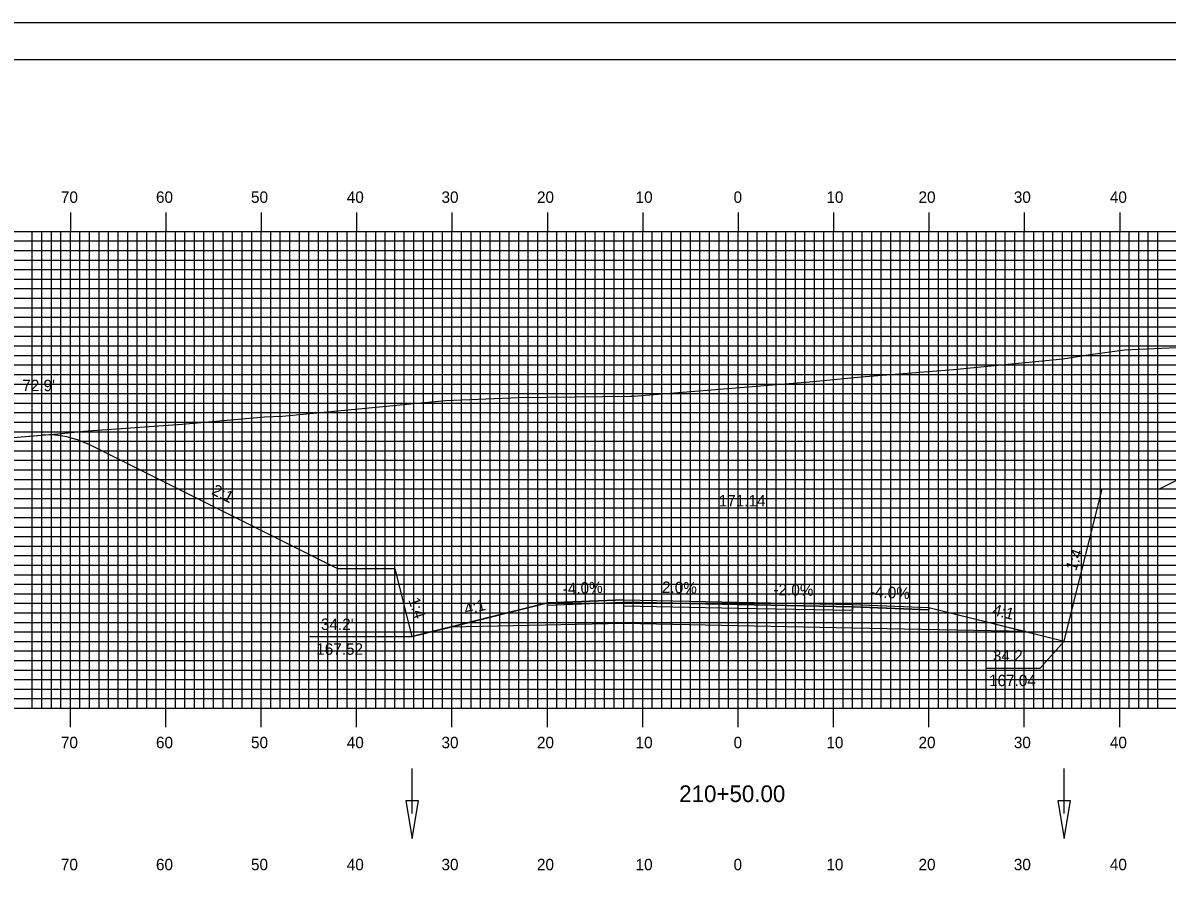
# Model space of a CAD drawing. Extents: x 1794453 to 1794796, y 442591 to 442811.
# Drawn here: x 1794543.4 to 1794663.3, y 442721.2 to 442810.5 of the extents above; entities that cross this region are included whole.
import ezdxf

# ---------------------------------------------------------------- set-up
doc = ezdxf.new("R2010")
doc.units = 0
for name, color, linetype in [('ANNOTATION', 7, 'Continuous'), ('BORDER', 7, 'Continuous'), ('D_Drainage_Ditch_Line', 7, 'Continuous'), ('D_Roadway_Centerline', 7, 'Continuous'), ('D_Roadway_Centerline_Text', 7, 'Continuous'), ('D_Roadway_Edge_Shoulder', 7, 'Continuous'), ('D_Roadway_Edge_TW', 7, 'Continuous'), ('D_Roadway_FinishedGrade', 7, 'Continuous'), ('D_Roadway_Pavement', 7, 'Continuous'), ('D_Roadway_SlopeLines', 7, 'Continuous'), ('D_Roadway_SubGrade', 7, 'Continuous'), ('D_Text_Standard', 7, 'Continuous'), ('H_V ANNOTATION', 7, 'Continuous'), ('MAJOR', 7, 'Continuous'), ('MINOR', 7, 'Continuous'), ('PDRAIN', 7, 'Continuous'), ('PLOT BOUNDARY', 7, 'Continuous'), ('S_Roadway_Centerline', 7, 'Continuous')]:
    doc.layers.add(name, color=color, linetype=linetype)

msp = doc.modelspace()

# ---------------------------------------------------------------- linework, layer by layer
at = {"layer": 'ANNOTATION'}
msp.add_lwpolyline([(1794644.32, 442742.86), (1794650.01, 442742.86), (1794652.51, 442745.7)], dxfattribs=at)
at = {"layer": 'BORDER'}
msp.add_lwpolyline([(1794468.74, 442596.67), (1794788.74, 442596.67), (1794788.74, 442806.67), (1794468.74, 442806.67)], close=True, dxfattribs=at)
at = {"layer": 'D_Drainage_Ditch_Line'}
for p, q in [((1794584.17, 442727.63), (1794584.17, 442732.33)), ((1794652.51, 442727.63), (1794652.51, 442732.33))]:
    msp.add_line(p, q, dxfattribs=at)
for points in [[(1794584.82, 442728.94), (1794583.51, 442728.94), (1794584.17, 442725)], [(1794653.17, 442728.94), (1794651.86, 442728.94), (1794652.51, 442725)]]:
    msp.add_lwpolyline(points, close=True, dxfattribs=at)
at = {"layer": 'D_Roadway_Centerline'}
msp.add_lwpolyline([(1794584.17, 442746.18), (1794588.17, 442747.18), (1794598.34, 442749.72), (1794606.34, 442750.04), (1794618.34, 442749.8), (1794630.34, 442749.56), (1794638.34, 442749.24), (1794648.51, 442746.7), (1794652.51, 442745.7)], dxfattribs=at)
at = {"layer": 'D_Roadway_Edge_Shoulder'}
for points in [[(1794606.34, 442750.04), (1794598.34, 442749.72), (1794598.34, 442749.47), (1794606.34, 442749.79)], [(1794630.34, 442749.56), (1794638.34, 442749.24), (1794638.34, 442748.99), (1794630.34, 442749.31)]]:
    msp.add_lwpolyline(points, close=True, dxfattribs=at)
at = {"layer": 'D_Roadway_Edge_TW'}
msp.add_lwpolyline([(1794606.34, 442749.79), (1794606.34, 442750.04), (1794618.34, 442749.8), (1794630.34, 442749.56), (1794630.34, 442749.31), (1794618.34, 442749.55)], close=True, dxfattribs=at)
at = {"layer": 'D_Roadway_FinishedGrade'}
msp.add_arc((1794545.9, 442757.33), 10, 63.4349, 92.7287, dxfattribs=at)
at = {"layer": 'D_Roadway_Pavement'}
msp.add_lwpolyline([(1794606.34, 442749.38), (1794606.34, 442749.79), (1794618.34, 442749.55), (1794630.34, 442749.31), (1794630.34, 442748.9), (1794618.34, 442749.14)], close=True, dxfattribs=at)
at = {"layer": 'D_Roadway_SlopeLines'}
for p, q in [((1794662.5, 442761.67), (1794686.86, 442773.84)), ((1794652.51, 442745.7), (1794656.5, 442761.67)), ((1794656.5, 442761.67), (1794662.5, 442761.67))]:
    msp.add_line(p, q, dxfattribs=at)
for points in [[(1794582.39, 442753.27), (1794576.39, 442753.27), (1794550.37, 442766.28)], [(1794584.17, 442746.18), (1794582.39, 442753.27), (1794576.39, 442753.27)], [(1794598.34, 442749.72), (1794584.17, 442746.18)], [(1794638.34, 442749.24), (1794652.51, 442745.7)]]:
    msp.add_lwpolyline(points, dxfattribs=at)
at = {"layer": 'D_Roadway_SubGrade'}
msp.add_lwpolyline([(1794606.34, 442747.54), (1794588.17, 442747.18), (1794598.34, 442749.72), (1794598.34, 442749.47), (1794606.34, 442749.79), (1794618.34, 442749.55), (1794630.34, 442749.31), (1794638.34, 442748.99), (1794638.34, 442749.24), (1794648.51, 442746.7), (1794630.34, 442747.06), (1794618.34, 442747.3)], close=True, dxfattribs=at)
at = {"layer": 'MAJOR'}
for p, q in [((1794548.34, 442790.67), (1794548.34, 442788.67)), ((1794558.34, 442790.67), (1794558.34, 442788.67)), ((1794568.34, 442790.67), (1794568.34, 442788.67)), ((1794578.34, 442790.67), (1794578.34, 442788.67)), ((1794588.34, 442790.67), (1794588.34, 442788.67)), ((1794598.34, 442790.67), (1794598.34, 442788.67)), ((1794608.34, 442790.67), (1794608.34, 442788.67)), ((1794618.34, 442790.67), (1794618.34, 442788.67)), ((1794628.34, 442790.67), (1794628.34, 442788.67)), ((1794638.34, 442790.67), (1794638.34, 442788.67)), ((1794648.34, 442790.67), (1794648.34, 442788.67)), ((1794658.34, 442790.67), (1794658.34, 442788.67)), ((1794478.34, 442788.67), (1794758.34, 442788.67)), ((1794478.34, 442788.67), (1794758.34, 442788.67)), ((1794548.34, 442738.67), (1794548.34, 442788.67)), ((1794558.34, 442738.67), (1794558.34, 442788.67)), ((1794568.34, 442738.67), (1794568.34, 442788.67)), ((1794578.34, 442738.67), (1794578.34, 442788.67)), ((1794588.34, 442738.67), (1794588.34, 442788.67)), ((1794598.34, 442738.67), (1794598.34, 442788.67)), ((1794608.34, 442738.67), (1794608.34, 442788.67)), ((1794618.34, 442738.67), (1794618.34, 442788.67)), ((1794628.34, 442738.67), (1794628.34, 442788.67)), ((1794638.34, 442738.67), (1794638.34, 442788.67)), ((1794648.34, 442738.67), (1794648.34, 442788.67)), ((1794658.34, 442738.67), (1794658.34, 442788.67)), ((1794478.34, 442783.67), (1794758.34, 442783.67)), ((1794478.34, 442778.67), (1794758.34, 442778.67)), ((1794478.34, 442773.67), (1794758.34, 442773.67)), ((1794478.34, 442768.67), (1794758.34, 442768.67)), ((1794478.34, 442763.67), (1794758.34, 442763.67)), ((1794478.34, 442758.67), (1794758.34, 442758.67)), ((1794478.34, 442753.67), (1794758.34, 442753.67)), ((1794478.34, 442748.67), (1794758.34, 442748.67)), ((1794478.34, 442743.67), (1794758.34, 442743.67)), ((1794478.34, 442738.67), (1794758.34, 442738.67)), ((1794478.34, 442738.67), (1794758.34, 442738.67)), ((1794548.34, 442736.66), (1794548.34, 442738.67)), ((1794558.34, 442736.66), (1794558.34, 442738.67)), ((1794568.34, 442736.66), (1794568.34, 442738.67)), ((1794578.34, 442736.66), (1794578.34, 442738.67)), ((1794588.34, 442736.66), (1794588.34, 442738.67)), ((1794598.34, 442736.66), (1794598.34, 442738.67)), ((1794608.34, 442736.66), (1794608.34, 442738.67)), ((1794618.34, 442736.66), (1794618.34, 442738.67)), ((1794628.34, 442736.66), (1794628.34, 442738.67)), ((1794638.34, 442736.66), (1794638.34, 442738.67)), ((1794648.34, 442736.66), (1794648.34, 442738.67)), ((1794658.34, 442736.66), (1794658.34, 442738.67))]:
    msp.add_line(p, q, dxfattribs=at)
at = {"layer": 'MINOR'}
for p, q in [((1794544.34, 442738.67), (1794544.34, 442788.67)), ((1794545.34, 442738.67), (1794545.34, 442788.67)), ((1794546.34, 442738.67), (1794546.34, 442788.67)), ((1794547.34, 442738.67), (1794547.34, 442788.67)), ((1794549.34, 442738.67), (1794549.34, 442788.67)), ((1794550.34, 442738.67), (1794550.34, 442788.67)), ((1794551.34, 442738.67), (1794551.34, 442788.67)), ((1794552.34, 442738.67), (1794552.34, 442788.67)), ((1794553.34, 442738.67), (1794553.34, 442788.67)), ((1794554.34, 442738.67), (1794554.34, 442788.67)), ((1794555.34, 442738.67), (1794555.34, 442788.67)), ((1794556.34, 442738.67), (1794556.34, 442788.67)), ((1794557.34, 442738.67), (1794557.34, 442788.67)), ((1794559.34, 442738.67), (1794559.34, 442788.67)), ((1794560.34, 442738.67), (1794560.34, 442788.67)), ((1794561.34, 442738.67), (1794561.34, 442788.67)), ((1794562.34, 442738.67), (1794562.34, 442788.67)), ((1794563.34, 442738.67), (1794563.34, 442788.67)), ((1794564.34, 442738.67), (1794564.34, 442788.67)), ((1794565.34, 442738.67), (1794565.34, 442788.67)), ((1794566.34, 442738.67), (1794566.34, 442788.67)), ((1794567.34, 442738.67), (1794567.34, 442788.67)), ((1794569.34, 442738.67), (1794569.34, 442788.67)), ((1794570.34, 442738.67), (1794570.34, 442788.67)), ((1794571.34, 442738.67), (1794571.34, 442788.67)), ((1794572.34, 442738.67), (1794572.34, 442788.67)), ((1794573.34, 442738.67), (1794573.34, 442788.67)), ((1794574.34, 442738.67), (1794574.34, 442788.67)), ((1794575.34, 442738.67), (1794575.34, 442788.67)), ((1794576.34, 442738.67), (1794576.34, 442788.67)), ((1794577.34, 442738.67), (1794577.34, 442788.67)), ((1794579.34, 442738.67), (1794579.34, 442788.67)), ((1794580.34, 442738.67), (1794580.34, 442788.67)), ((1794581.34, 442738.67), (1794581.34, 442788.67)), ((1794582.34, 442738.67), (1794582.34, 442788.67)), ((1794583.34, 442738.67), (1794583.34, 442788.67)), ((1794584.34, 442738.67), (1794584.34, 442788.67)), ((1794585.34, 442738.67), (1794585.34, 442788.67)), ((1794586.34, 442738.67), (1794586.34, 442788.67)), ((1794587.34, 442738.67), (1794587.34, 442788.67)), ((1794589.34, 442738.67), (1794589.34, 442788.67)), ((1794590.34, 442738.67), (1794590.34, 442788.67)), ((1794591.34, 442738.67), (1794591.34, 442788.67)), ((1794592.34, 442738.67), (1794592.34, 442788.67)), ((1794593.34, 442738.67), (1794593.34, 442788.67)), ((1794594.34, 442738.67), (1794594.34, 442788.67)), ((1794595.34, 442738.67), (1794595.34, 442788.67)), ((1794596.34, 442738.67), (1794596.34, 442788.67)), ((1794597.34, 442738.67), (1794597.34, 442788.67)), ((1794599.34, 442738.67), (1794599.34, 442788.67)), ((1794600.34, 442738.67), (1794600.34, 442788.67)), ((1794601.34, 442738.67), (1794601.34, 442788.67)), ((1794602.34, 442738.67), (1794602.34, 442788.67)), ((1794603.34, 442738.67), (1794603.34, 442788.67)), ((1794604.34, 442738.67), (1794604.34, 442788.67)), ((1794605.34, 442738.67), (1794605.34, 442788.67)), ((1794606.34, 442738.67), (1794606.34, 442788.67)), ((1794607.34, 442738.67), (1794607.34, 442788.67)), ((1794609.34, 442738.67), (1794609.34, 442788.67)), ((1794610.34, 442738.67), (1794610.34, 442788.67)), ((1794611.34, 442738.67), (1794611.34, 442788.67)), ((1794612.34, 442738.67), (1794612.34, 442788.67)), ((1794613.34, 442738.67), (1794613.34, 442788.67)), ((1794614.34, 442738.67), (1794614.34, 442788.67)), ((1794615.34, 442738.67), (1794615.34, 442788.67)), ((1794616.34, 442738.67), (1794616.34, 442788.67)), ((1794617.34, 442738.67), (1794617.34, 442788.67)), ((1794619.34, 442738.67), (1794619.34, 442788.67)), ((1794620.34, 442738.67), (1794620.34, 442788.67)), ((1794621.34, 442738.67), (1794621.34, 442788.67)), ((1794622.34, 442738.67), (1794622.34, 442788.67)), ((1794623.34, 442738.67), (1794623.34, 442788.67)), ((1794624.34, 442738.67), (1794624.34, 442788.67)), ((1794625.34, 442738.67), (1794625.34, 442788.67)), ((1794626.34, 442738.67), (1794626.34, 442788.67)), ((1794627.34, 442738.67), (1794627.34, 442788.67)), ((1794629.34, 442738.67), (1794629.34, 442788.67)), ((1794630.34, 442738.67), (1794630.34, 442788.67)), ((1794631.34, 442738.67), (1794631.34, 442788.67)), ((1794632.34, 442738.67), (1794632.34, 442788.67)), ((1794633.34, 442738.67), (1794633.34, 442788.67)), ((1794634.34, 442738.67), (1794634.34, 442788.67)), ((1794635.34, 442738.67), (1794635.34, 442788.67)), ((1794636.34, 442738.67), (1794636.34, 442788.67)), ((1794637.34, 442738.67), (1794637.34, 442788.67)), ((1794639.34, 442738.67), (1794639.34, 442788.67)), ((1794640.34, 442738.67), (1794640.34, 442788.67)), ((1794641.34, 442738.67), (1794641.34, 442788.67)), ((1794642.34, 442738.67), (1794642.34, 442788.67)), ((1794643.34, 442738.67), (1794643.34, 442788.67)), ((1794644.34, 442738.67), (1794644.34, 442788.67)), ((1794645.34, 442738.67), (1794645.34, 442788.67)), ((1794646.34, 442738.67), (1794646.34, 442788.67)), ((1794647.34, 442738.67), (1794647.34, 442788.67)), ((1794649.34, 442738.67), (1794649.34, 442788.67)), ((1794650.34, 442738.67), (1794650.34, 442788.67)), ((1794651.34, 442738.67), (1794651.34, 442788.67)), ((1794652.34, 442738.67), (1794652.34, 442788.67)), ((1794653.34, 442738.67), (1794653.34, 442788.67)), ((1794654.34, 442738.67), (1794654.34, 442788.67)), ((1794655.34, 442738.67), (1794655.34, 442788.67)), ((1794656.34, 442738.67), (1794656.34, 442788.67)), ((1794657.34, 442738.67), (1794657.34, 442788.67)), ((1794659.34, 442738.67), (1794659.34, 442788.67)), ((1794660.34, 442738.67), (1794660.34, 442788.67)), ((1794661.34, 442738.67), (1794661.34, 442788.67)), ((1794662.34, 442738.67), (1794662.34, 442788.67)), ((1794478.34, 442787.67), (1794758.34, 442787.67)), ((1794478.34, 442786.67), (1794758.34, 442786.67)), ((1794478.34, 442785.67), (1794758.34, 442785.67)), ((1794478.34, 442784.67), (1794758.34, 442784.67)), ((1794478.34, 442782.67), (1794758.34, 442782.67)), ((1794478.34, 442781.67), (1794758.34, 442781.67)), ((1794478.34, 442780.67), (1794758.34, 442780.67)), ((1794478.34, 442779.67), (1794758.34, 442779.67)), ((1794478.34, 442777.67), (1794758.34, 442777.67)), ((1794478.34, 442776.67), (1794758.34, 442776.67)), ((1794478.34, 442775.67), (1794758.34, 442775.67)), ((1794478.34, 442774.67), (1794758.34, 442774.67)), ((1794478.34, 442772.67), (1794758.34, 442772.67)), ((1794478.34, 442771.67), (1794758.34, 442771.67)), ((1794478.34, 442770.67), (1794758.34, 442770.67)), ((1794478.34, 442769.67), (1794758.34, 442769.67)), ((1794478.34, 442767.67), (1794758.34, 442767.67)), ((1794478.34, 442766.67), (1794758.34, 442766.67)), ((1794478.34, 442765.67), (1794758.34, 442765.67)), ((1794478.34, 442764.67), (1794758.34, 442764.67)), ((1794478.34, 442762.67), (1794758.34, 442762.67)), ((1794478.34, 442761.67), (1794758.34, 442761.67)), ((1794478.34, 442760.67), (1794758.34, 442760.67)), ((1794478.34, 442759.67), (1794758.34, 442759.67)), ((1794478.34, 442757.67), (1794758.34, 442757.67)), ((1794478.34, 442756.67), (1794758.34, 442756.67)), ((1794478.34, 442755.67), (1794758.34, 442755.67)), ((1794478.34, 442754.67), (1794758.34, 442754.67)), ((1794478.34, 442752.67), (1794758.34, 442752.67)), ((1794478.34, 442751.67), (1794758.34, 442751.67)), ((1794478.34, 442750.67), (1794758.34, 442750.67)), ((1794478.34, 442749.67), (1794758.34, 442749.67)), ((1794478.34, 442747.67), (1794758.34, 442747.67)), ((1794478.34, 442746.67), (1794758.34, 442746.67)), ((1794478.34, 442745.67), (1794758.34, 442745.67)), ((1794478.34, 442744.67), (1794758.34, 442744.67)), ((1794478.34, 442742.67), (1794758.34, 442742.67)), ((1794478.34, 442741.67), (1794758.34, 442741.67)), ((1794478.34, 442740.67), (1794758.34, 442740.67)), ((1794478.34, 442739.67), (1794758.34, 442739.67))]:
    msp.add_line(p, q, dxfattribs=at)
at = {"layer": 'PDRAIN'}
msp.add_line((1794573.44, 442746.18), (1794584.17, 442746.18), dxfattribs=at)
at = {"layer": 'PLOT BOUNDARY'}
msp.add_lwpolyline([(1794452.55, 442590.55), (1794792.55, 442590.55), (1794792.55, 442810.55), (1794452.55, 442810.55)], close=True, dxfattribs=at)
at = {"layer": 'S_Roadway_Centerline'}
msp.add_lwpolyline([(1794541.92, 442767.04), (1794547.45, 442767.48), (1794549.7, 442767.71), (1794560.05, 442768.47), (1794568.69, 442769.23), (1794570.58, 442769.31), (1794574.18, 442769.66), (1794587.66, 442770.93), (1794595.36, 442771.27), (1794607.06, 442771.39), (1794607.36, 442771.41), (1794625.82, 442772.9), (1794631.23, 442773.41), (1794640.93, 442774.18), (1794644.86, 442774.57), (1794652.38, 442775.32), (1794655.23, 442775.75), (1794658.84, 442776.27), (1794665.09, 442776.54)], dxfattribs=at)

# ---------------------------------------------------------------- texts
at = {"layer": 'ANNOTATION'}
for s, rotation, p in [('2:1', 333.4349, (1794563.05, 442761.15)), ('2:1', 333.4349, (1794563.05, 442761.15)), ('1:4', 70.516, (1794653.76, 442752.99)), ('1:4', 70.516, (1794653.76, 442752.99)), ('-4.0%', 2.2906, (1794599.97, 442750.59)), ('2.0%', 358.8542, (1794610.35, 442750.76)), ('-2.0%', 358.8542, (1794622.03, 442750.53)), ('-4.0%', 357.7094, (1794632.13, 442750.29)), ('1:4', 289.484, (1794583.74, 442750.04)), ('1:4', 289.484, (1794583.74, 442750.04)), ('4:1', 14.0362, (1794589.79, 442748.45)), ('4:1', 345.9638, (1794644.93, 442748.46))]:
    msp.add_text(s, height=1.2, rotation=rotation, dxfattribs=at).set_placement(p)
for s, p in [("34.2'", (1794574.6, 442746.87)), ('167.52', (1794574.11, 442744.27)), ("34.2'", (1794645.05, 442743.58)), ('167.04', (1794644.64, 442740.98))]:
    msp.add_text(s, height=1.2, dxfattribs=at).set_placement(p)
at = {"layer": 'D_Roadway_Centerline'}
for s, p in [('C', (1794618.33, 442749.8)), ('L', (1794618.34, 442749.8))]:
    msp.add_text(s, height=0.0146, dxfattribs=at).set_placement(p)
at = {"layer": 'D_Roadway_Centerline_Text'}
msp.add_text('171.14', height=1.2, dxfattribs=at).set_placement((1794616.3, 442759.83))
at = {"layer": 'D_Text_Standard'}
msp.add_text("72.9'", height=1.2, dxfattribs=at).set_placement((1794543.29, 442771.92))
at = {"layer": 'H_V ANNOTATION'}
for s, height, p in [('70', 1.2, (1794547.34, 442791.67)), ('60', 1.2, (1794557.31, 442791.67)), ('50', 1.2, (1794567.27, 442791.67)), ('40', 1.2, (1794577.31, 442791.67)), ('30', 1.2, (1794587.24, 442791.67)), ('20', 1.2, (1794597.25, 442791.67)), ('10', 1.2, (1794607.59, 442791.67)), ('0', 1.2, (1794617.86, 442791.67)), ('10', 1.2, (1794627.59, 442791.67)), ('20', 1.2, (1794637.25, 442791.67)), ('30', 1.2, (1794647.24, 442791.67)), ('40', 1.2, (1794657.31, 442791.67)), ('70', 1.2, (1794547.34, 442734.47)), ('60', 1.2, (1794557.31, 442734.47)), ('50', 1.2, (1794567.27, 442734.47)), ('40', 1.2, (1794577.31, 442734.47)), ('30', 1.2, (1794587.24, 442734.47)), ('20', 1.2, (1794597.25, 442734.47)), ('10', 1.2, (1794607.59, 442734.47)), ('0', 1.2, (1794617.86, 442734.47)), ('10', 1.2, (1794627.59, 442734.47)), ('20', 1.2, (1794637.25, 442734.47)), ('30', 1.2, (1794647.24, 442734.47)), ('40', 1.2, (1794657.31, 442734.47)), ('210+50.00', 1.75, (1794612.16, 442728.82)), ('70', 1.2, (1794547.34, 442721.67)), ('60', 1.2, (1794557.31, 442721.67)), ('50', 1.2, (1794567.27, 442721.67)), ('40', 1.2, (1794577.31, 442721.67)), ('30', 1.2, (1794587.24, 442721.67)), ('20', 1.2, (1794597.25, 442721.67)), ('10', 1.2, (1794607.59, 442721.67)), ('0', 1.2, (1794617.86, 442721.67)), ('10', 1.2, (1794627.59, 442721.67)), ('20', 1.2, (1794637.25, 442721.67)), ('30', 1.2, (1794647.24, 442721.67)), ('40', 1.2, (1794657.31, 442721.67))]:
    msp.add_text(s, height=height, dxfattribs=at).set_placement(p)

doc.saveas('drawing.dxf')
